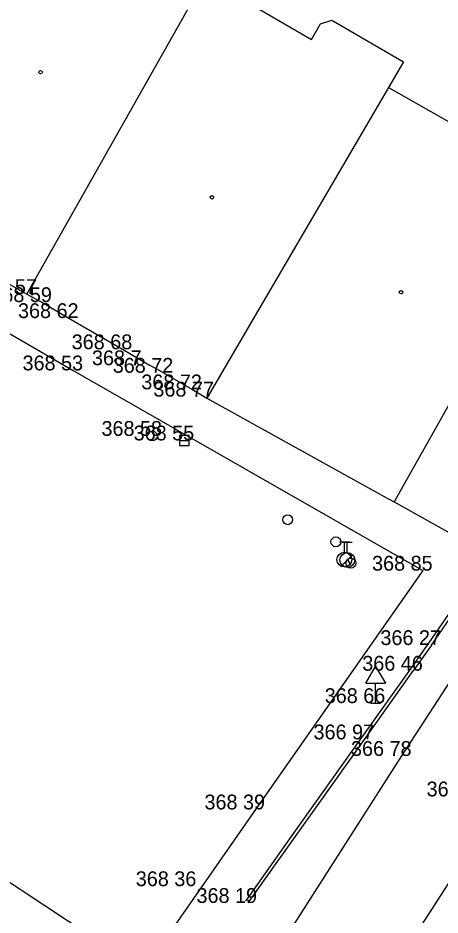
# Model space of a CAD drawing. Extents: x -688316 to -688024, y -973785 to -973591.
# Drawn here: x -688108.72 to -688087.33, y -973675.68 to -973630.22 of the extents above; entities that cross this region are included whole.
import ezdxf

# ---------------------------------------------------------------- set-up
doc = ezdxf.new("R2010")
doc.units = 0
for name, color, linetype in [('Vrstva 10', 7, 'Continuous'), ('Vrstva 27', 7, 'Continuous'), ('Vrstva 28_Verejne osvetleni', 7, 'Continuous'), ('Vrstva 3', 7, 'Continuous'), ('Vrstva 34', 7, 'Continuous'), ('Vrstva 5', 7, 'Continuous'), ('Vrstva 58', 7, 'Continuous'), ('Vrstva 6', 7, 'Continuous'), ('Vrstva 8', 7, 'Continuous'), ('Vrstva 9', 7, 'Continuous')]:
    doc.layers.add(name, color=color, linetype=linetype)

# ---------------------------------------------------------------- blocks, each defined once
blk = doc.blocks.new('B_NESP')
at = {"layer": 'Vrstva 58'}
blk.add_circle((0, 0), 0.875, dxfattribs=at)
blk = doc.blocks.new('DZ')
at = {"layer": 'Vrstva 34'}
for p, q in [((-5, 10), (0, 18.5)), ((0, 18.5), (5, 10)), ((-5, 10), (5, 10)), ((0, 0), (0, 10)), ((-2.49, 0), (2.49, 0))]:
    blk.add_line(p, q, dxfattribs=at)
blk = doc.blocks.new('SV')
at = {"layer": 'Vrstva 28_Verejne osvetleni'}
blk.add_circle((0, 0), 2.5, dxfattribs=at)
blk = doc.blocks.new('HYN')
at = {"layer": 'Vrstva 28_Verejne osvetleni'}
for p, q in [((-2.5, 8.99), (2.5, 8.99)), ((0, 3.75), (0, 8.99))]:
    blk.add_line(p, q, dxfattribs=at)
blk.add_circle((0, 0), 3.75, dxfattribs=at)
blk = doc.blocks.new('VP')
at = {"layer": 'Vrstva 27'}
blk.add_line((-2.5, 0), (2.5, 0), dxfattribs=at)
blk.add_lwpolyline([(-2.5, -2.5), (2.5, -2.5), (2.5, 2.5), (-2.5, 2.5)], close=True, dxfattribs=at)
blk = doc.blocks.new('HYP')
at = {"layer": 'Vrstva 28_Verejne osvetleni'}
for p, q in [((-2.5, 8.99), (2.5, 8.99)), ((0, 3.75), (0, 8.99)), ((-2.65, -2.65), (2.65, 2.65))]:
    blk.add_line(p, q, dxfattribs=at)
blk.add_circle((0, 0), 3.75, dxfattribs=at)

msp = doc.modelspace()

# ---------------------------------------------------------------- linework, layer by layer
at = {"layer": 'Vrstva 10'}
for p, q in [((-688116.85, -973641.76), (-688105.92, -973648.08)), ((-688105.92, -973648.08), (-688088.21, -973658.23)), ((-688089.26, -973667.62), (-688076.78, -973648.31)), ((-688087.77, -973662), (-688084.68, -973657.51)), ((-688088.21, -973658.23), (-688096.69, -973670.33)), ((-688091.16, -973666.78), (-688088.69, -973663.3)), ((-688088.66, -973676.81), (-688080.87, -973664.7)), ((-688097.05, -973675.07), (-688091.16, -973666.78)), ((-688102.38, -973678.5), (-688119.12, -973667.46)), ((-688097.29, -973680.17), (-688089.26, -973667.62)), ((-688096.69, -973670.33), (-688102.38, -973678.5))]:
    msp.add_line(p, q, dxfattribs=at)
at = {"layer": 'Vrstva 5'}
for p, q in [((-688108.26, -973644.21), (-688099.22, -973628.18)), ((-688098.77, -973628.44), (-688093.85, -973631.31)), ((-688093.85, -973631.31), (-688093.39, -973630.52)), ((-688093.39, -973630.52), (-688092.82, -973630.33)), ((-688092.82, -973630.33), (-688089.19, -973632.45)), ((-688089.19, -973632.45), (-688089.95, -973633.75)), ((-688089.95, -973633.75), (-688099.15, -973649.49)), ((-688089.95, -973633.75), (-688082.42, -973638.02)), ((-688108.26, -973644.21), (-688107.5, -973644.62)), ((-688106.14, -973645.43), (-688103.42, -973647.01)), ((-688101.35, -973648.2), (-688102.05, -973647.82)), ((-688099.9, -973649.04), (-688099.29, -973649.41))]:
    msp.add_line(p, q, dxfattribs=at)
for points in [[(-688079.48, -973636.64), (-688085.61, -973647.54), (-688089.66, -973654.75)], [(-688109.33, -973643.32), (-688109.22, -973643.68), (-688108.26, -973644.21)], [(-688099.29, -973649.41), (-688099.15, -973649.49), (-688090.01, -973654.56), (-688089.66, -973654.75), (-688084.82, -973657.44), (-688084.68, -973657.51), (-688084.54, -973657.59), (-688084.06, -973656.78), (-688084.31, -973656.63), (-688083.55, -973655.36), (-688083.28, -973655.43), (-688082.86, -973654.77)], [(-688092.029, -973657.69), (-688091.897, -973657.876)]]:
    msp.add_lwpolyline(points, dxfattribs=at)
at = {"layer": 'Vrstva 6'}
for p, q in [((-688107.5, -973644.62), (-688106.14, -973645.43)), ((-688103.42, -973647.01), (-688102.05, -973647.82)), ((-688101.35, -973648.2), (-688099.9, -973649.04))]:
    msp.add_line(p, q, dxfattribs=at)
at = {"layer": 'Vrstva 8'}
msp.add_line((-688087.77, -973662), (-688088.69, -973663.3), dxfattribs=at)
at = {"layer": 'Vrstva 9'}
for points in [[(-688088.82, -973663.21), (-688087.9, -973661.91), (-688084.82, -973657.44)], [(-688097.18, -973674.98), (-688094.82, -973671.66), (-688091.29, -973666.69), (-688088.82, -973663.21)]]:
    msp.add_lwpolyline(points, dxfattribs=at)

# ---------------------------------------------------------------- block references
at = {"layer": 'Vrstva 27', "xscale": 0.1, "yscale": 0.10000000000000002}
msp.add_blockref('VP', (-688100.29, -973651.63), dxfattribs=at)
at = {"layer": 'Vrstva 28_Verejne osvetleni', "xscale": 0.1, "yscale": 0.10000000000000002}
for name, p in [('SV', (-688101.92, -973651.4)), ('SV', (-688095.05, -973655.65)), ('SV', (-688092.61, -973656.77)), ('HYN', (-688092.18, -973657.67)), ('HYP', (-688092.03, -973657.69)), ('SV', (-688091.85, -973657.85))]:
    msp.add_blockref(name, p, dxfattribs=at)
at = {"layer": 'Vrstva 34', "xscale": 0.1, "yscale": 0.10000000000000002}
msp.add_blockref('DZ', (-688090.6, -973664.94), dxfattribs=at)
msp.add_blockref('DZ', (-688090.6, -973664.94), dxfattribs=at)
msp.add_blockref('DZ', (-688090.6, -973664.94), dxfattribs=at)
msp.add_blockref('DZ', (-688090.6, -973664.94), dxfattribs=at)
at = {"layer": 'Vrstva 58', "xscale": 0.1, "yscale": 0.10000000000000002}
for p in [(-688107.57, -973632.97), (-688107.57, -973632.97), (-688107.57, -973632.97), (-688107.57, -973632.97), (-688098.89, -973639.31), (-688098.89, -973639.31), (-688098.89, -973639.31), (-688098.89, -973639.31), (-688089.31, -973644.12), (-688089.31, -973644.12), (-688089.31, -973644.12), (-688089.31, -973644.12)]:
    msp.add_blockref('B_NESP', p, dxfattribs=at)

# ---------------------------------------------------------------- texts
at = {"layer": 'Vrstva 3'}
for s, p in [('368 57 ', (-688110.826, -973644.21)), ('368 57 ', (-688110.826, -973644.21)), ('368 57 ', (-688110.826, -973644.21)), ('368 57 ', (-688110.826, -973644.21)), ('368 57 ', (-688110.826, -973644.21)), ('368 57 ', (-688110.826, -973644.21)), ('368 57 ', (-688110.826, -973644.21)), ('368 59 ', (-688110.066, -973644.62)), ('368 59 ', (-688110.066, -973644.62)), ('368 59 ', (-688110.066, -973644.62)), ('368 59 ', (-688110.066, -973644.62)), ('368 59 ', (-688110.066, -973644.62)), ('368 59 ', (-688110.066, -973644.62)), ('368 59 ', (-688110.066, -973644.62)), ('368 62 ', (-688108.715, -973645.43)), ('368 62 ', (-688108.715, -973645.43)), ('368 62 ', (-688108.715, -973645.43)), ('368 62 ', (-688108.715, -973645.43)), ('368 62 ', (-688108.715, -973645.43)), ('368 62 ', (-688108.715, -973645.43)), ('368 62 ', (-688108.715, -973645.43)), ('368 68 ', (-688105.995, -973647.01)), ('368 68 ', (-688105.995, -973647.01)), ('368 68 ', (-688105.995, -973647.01)), ('368 68 ', (-688105.995, -973647.01)), ('368 68 ', (-688105.995, -973647.01)), ('368 68 ', (-688105.995, -973647.01)), ('368 68 ', (-688105.995, -973647.01)), ('368 53 ', (-688108.486, -973648.08)), ('368 53 ', (-688108.486, -973648.08)), ('368 53 ', (-688108.486, -973648.08)), ('368 53 ', (-688108.486, -973648.08)), ('368 53 ', (-688108.486, -973648.08)), ('368 53 ', (-688108.486, -973648.08)), ('368 53 ', (-688108.486, -973648.08)), ('368 7  ', (-688104.967, -973647.82)), ('368 7  ', (-688104.967, -973647.82)), ('368 7  ', (-688104.967, -973647.82)), ('368 7  ', (-688104.967, -973647.82)), ('368 7  ', (-688104.967, -973647.82)), ('368 7  ', (-688104.967, -973647.82)), ('368 7  ', (-688104.967, -973647.82)), ('368 72 ', (-688103.916, -973648.2)), ('368 72 ', (-688103.916, -973648.2)), ('368 72 ', (-688103.916, -973648.2)), ('368 72 ', (-688103.916, -973648.2)), ('368 72 ', (-688103.916, -973648.2)), ('368 72 ', (-688103.916, -973648.2)), ('368 72 ', (-688103.916, -973648.2)), ('368 72 ', (-688102.466, -973649.04)), ('368 72 ', (-688102.466, -973649.04)), ('368 72 ', (-688102.466, -973649.04)), ('368 72 ', (-688102.466, -973649.04)), ('368 72 ', (-688102.466, -973649.04)), ('368 72 ', (-688102.466, -973649.04)), ('368 72 ', (-688102.466, -973649.04)), ('368 77 ', (-688101.856, -973649.41)), ('368 77 ', (-688101.856, -973649.41)), ('368 77 ', (-688101.856, -973649.41)), ('368 77 ', (-688101.856, -973649.41)), ('368 77 ', (-688101.856, -973649.41)), ('368 77 ', (-688101.856, -973649.41)), ('368 77 ', (-688101.856, -973649.41)), ('368 58 ', (-688104.486, -973651.4)), ('368 58 ', (-688104.486, -973651.4)), ('368 58 ', (-688104.486, -973651.4)), ('368 58 ', (-688104.486, -973651.4)), ('368 58 ', (-688104.486, -973651.4)), ('368 58 ', (-688104.486, -973651.4)), ('368 58 ', (-688104.486, -973651.4)), ('368 55 ', (-688102.856, -973651.63)), ('368 55 ', (-688102.856, -973651.63)), ('368 55 ', (-688102.856, -973651.63)), ('368 55 ', (-688102.856, -973651.63)), ('368 55 ', (-688102.856, -973651.63)), ('368 55 ', (-688102.856, -973651.63)), ('368 55 ', (-688102.856, -973651.63)), ('368 85 ', (-688090.776, -973658.23)), ('368 85 ', (-688090.776, -973658.23)), ('368 85 ', (-688090.776, -973658.23)), ('368 85 ', (-688090.776, -973658.23)), ('368 85 ', (-688090.776, -973658.23)), ('368 85 ', (-688090.776, -973658.23)), ('368 85 ', (-688090.776, -973658.23)), ('366 27 ', (-688090.353, -973662)), ('366 27 ', (-688090.353, -973662)), ('366 27 ', (-688090.353, -973662)), ('366 27 ', (-688090.353, -973662)), ('366 27 ', (-688090.353, -973662)), ('366 27 ', (-688090.353, -973662)), ('366 27 ', (-688090.353, -973662)), ('366 46 ', (-688091.273, -973663.3)), ('366 46 ', (-688091.273, -973663.3)), ('366 46 ', (-688091.273, -973663.3)), ('366 46 ', (-688091.273, -973663.3)), ('366 46 ', (-688091.273, -973663.3)), ('366 46 ', (-688091.273, -973663.3)), ('366 46 ', (-688091.273, -973663.3)), ('368 66 ', (-688093.175, -973664.94)), ('368 66 ', (-688093.175, -973664.94)), ('368 66 ', (-688093.175, -973664.94)), ('368 66 ', (-688093.175, -973664.94)), ('368 66 ', (-688093.175, -973664.94)), ('368 66 ', (-688093.175, -973664.94)), ('368 66 ', (-688093.175, -973664.94)), ('366 97 ', (-688093.743, -973666.78)), ('366 97 ', (-688093.743, -973666.78)), ('366 97 ', (-688093.743, -973666.78)), ('366 97 ', (-688093.743, -973666.78)), ('366 97 ', (-688093.743, -973666.78)), ('366 97 ', (-688093.743, -973666.78)), ('366 97 ', (-688093.743, -973666.78)), ('366 78 ', (-688091.843, -973667.62)), ('366 78 ', (-688091.843, -973667.62)), ('366 78 ', (-688091.843, -973667.62)), ('366 78 ', (-688091.843, -973667.62)), ('366 78 ', (-688091.843, -973667.62)), ('366 78 ', (-688091.843, -973667.62)), ('366 78 ', (-688091.843, -973667.62)), ('366 75 ', (-688088.013, -973669.67)), ('366 75 ', (-688088.013, -973669.67)), ('366 75 ', (-688088.013, -973669.67)), ('366 75 ', (-688088.013, -973669.67)), ('366 75 ', (-688088.013, -973669.67)), ('366 75 ', (-688088.013, -973669.67)), ('366 75 ', (-688088.013, -973669.67)), ('368 39 ', (-688099.268, -973670.33)), ('368 39 ', (-688099.268, -973670.33)), ('368 39 ', (-688099.268, -973670.33)), ('368 39 ', (-688099.268, -973670.33)), ('368 39 ', (-688099.268, -973670.33)), ('368 39 ', (-688099.268, -973670.33)), ('368 39 ', (-688099.268, -973670.33)), ('368 36 ', (-688102.748, -973674.22)), ('368 36 ', (-688102.748, -973674.22)), ('368 36 ', (-688102.748, -973674.22)), ('368 36 ', (-688102.748, -973674.22)), ('368 36 ', (-688102.748, -973674.22)), ('368 36 ', (-688102.748, -973674.22)), ('368 36 ', (-688102.748, -973674.22)), ('368 19 ', (-688099.671, -973675.07)), ('368 19 ', (-688099.671, -973675.07)), ('368 19 ', (-688099.671, -973675.07)), ('368 19 ', (-688099.671, -973675.07)), ('368 19 ', (-688099.671, -973675.07)), ('368 19 ', (-688099.671, -973675.07)), ('368 19 ', (-688099.671, -973675.07))]:
    msp.add_text(s, height=0.75, dxfattribs=at).set_placement(p)

doc.saveas('drawing.dxf')
